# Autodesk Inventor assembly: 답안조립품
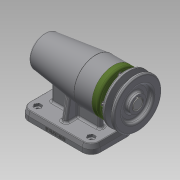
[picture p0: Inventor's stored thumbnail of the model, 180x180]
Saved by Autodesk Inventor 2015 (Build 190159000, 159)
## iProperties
Created: 2017-01
Part Number: 답안조립품
Document SubType Name: Assembly
Designer: Administrator
Author: Administrator
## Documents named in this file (12)
- C:\Users\Administrator\Desktop\470107V1015\답안조립품.iam
- C:\Users\Administrator\Desktop\470107V1015\본체.ipt
- C:\Users\Administrator\Desktop\470107V1015\V벨트풀리.ipt
- C:\Users\Administrator\Desktop\470107V1015\멈춤나사 M3x8.ipt
- C:\Users\Administrator\Desktop\470107V1015\베어링 6004.ipt
- C:\Users\Administrator\Desktop\470107V1015\베어링 51202.ipt
- C:\Users\Administrator\Desktop\470107V1015\볼트 M4 x 12.ipt
- C:\Users\Administrator\Desktop\470107V1015\어댑터슬리브.ipt
- C:\Users\Administrator\Desktop\470107V1015\오일 실.ipt
- C:\Users\Administrator\Desktop\470107V1015\축.ipt
- C:\Users\Administrator\Desktop\470107V1015\커버.ipt
- C:\Users\Administrator\Desktop\470107V1015\키 5 x 5 x 16.ipt
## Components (6 placed, 2 different names)
1. V벨트풀리:1
2. ISO 4762 M4 x 12:2
3. ISO 4762 M4 x 12:3
4. ISO 4762 M4 x 12:4
5. ISO 4762 M4 x 12:5
6. ISO 4762 M4 x 12:6
